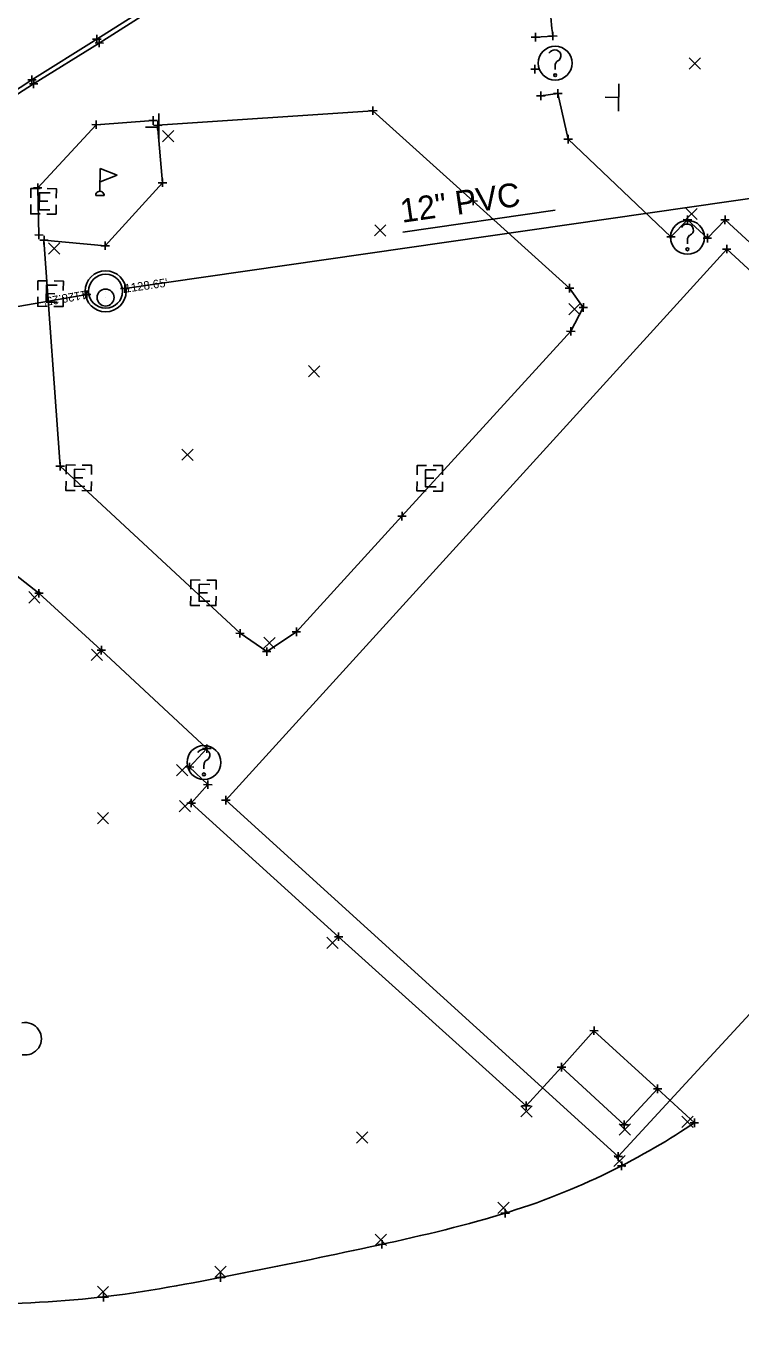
# Model space of a CAD drawing. Extents: x 142461 to 147261, y 511126 to 514697.
# Drawn here: x 145184.1 to 145268.4, y 512896.1 to 513050 of the extents above; entities that cross this region are included whole.
import ezdxf

# ---------------------------------------------------------------- set-up
doc = ezdxf.new("R2010")
doc.units = 0
for name, color, linetype in [('BD_X_Building', 7, 'Continuous'), ('DR_X_Cells', 7, 'Continuous'), ('DR_X_Elev_Flow', 7, 'Continuous'), ('DR_X_Storm_Sewer', 7, 'Continuous'), ('DR_X_Text', 7, 'Continuous'), ('GK_Drainage_Nodes', 7, 'Continuous'), ('PV_X_Curb', 7, 'Continuous'), ('PV_X_EOP', 7, 'Continuous'), ('PV_X_Walk', 7, 'Continuous'), ('RD_X_Cells', 7, 'Continuous'), ('RD_X_Misc_Items', 7, 'Continuous'), ('SC_Scratch1', 7, 'Continuous'), ('SN_X_Public', 7, 'Continuous'), ('SV_X_Random_Point', 7, 'Continuous'), ('SV_X_Shot_Marker', 7, 'Continuous'), ('UT_X_Electric_Cells', 7, 'Continuous'), ('VG_X_Cells', 7, 'Continuous')]:
    doc.layers.add(name, color=color, linetype=linetype)

msp = doc.modelspace()

# ---------------------------------------------------------------- linework, layer by layer
at = {"layer": 'BD_X_Building'}
msp.add_lwpolyline([(145253.97, 512916.68), (145313.24, 512980.9), (145266.75, 513023.71), (145207.7, 512958.7)], close=True, dxfattribs=at)
at = {"layer": 'DR_X_Cells'}
for centre, radius in [((145193.52, 513018.73), 2.42), ((145193.52, 513018.73), 2), ((145193.52, 513017.99), 1)]:
    msp.add_circle(centre, radius, dxfattribs=at)
at = {"layer": 'DR_X_Elev_Flow'}
for p, q in [((145190.79, 513018.34), (145191.79, 513018.34)), ((145191.29, 513018.84), (145191.29, 513017.84)), ((145191.29, 513018.34), (145191.29, 513018.34)), ((145195.28, 513019.06), (145196.28, 513019.06)), ((145195.78, 513019.56), (145195.78, 513018.56)), ((145195.78, 513019.06), (145195.78, 513019.06))]:
    msp.add_line(p, q, dxfattribs=at)
at = {"layer": 'DR_X_Storm_Sewer'}
for p, q in [((145195.78, 513019.06), (145275.88, 513030.6)), ((145191.29, 513018.34), (145030.57, 512990.68))]:
    msp.add_line(p, q, dxfattribs=at)
at = {"layer": 'DR_X_Text'}
msp.add_line((145246.52, 513028.29), (145228.56, 513025.7), dxfattribs=at)
at = {"layer": 'GK_Drainage_Nodes'}
for p, q in [((145193.52, 513020.74), (145193.52, 513020.74)), ((145193.52, 513018.73), (145193.52, 513018.73)), ((145193.52, 513018.73), (145193.52, 513018.73)), ((145193.52, 513017.99), (145193.52, 513017.99)), ((145193.52, 513016.74), (145193.52, 513016.74))]:
    msp.add_line(p, q, dxfattribs=at)
msp.add_circle((145193.52, 513018.73), 2, dxfattribs=at)
at = {"layer": 'PV_X_Curb'}
for p, q in [((145192.77, 513048.01), (145235.74, 513075.4)), ((145185.03, 513043.18), (145192.77, 513048.01)), ((145178.82, 513039.2), (145185.03, 513043.18))]:
    msp.add_line(p, q, dxfattribs=at)
msp.add_lwpolyline([(145186.25, 513024.75), (145193.47, 513024.1), (145200.22, 513031.53), (145199.65, 513038.31), (145225.04, 513040.03), (145236.86, 513029.37), (145248.21, 513019.09), (145249.84, 513016.82), (145248.38, 513014.01), (145228.46, 512992.2), (145216.01, 512978.56), (145212.52, 512976.23), (145209.37, 512978.39), (145188.17, 512998.09)], close=True, dxfattribs=at)
at = {"layer": 'PV_X_EOP'}
for p, q in [((145235.58, 513075.85), (145192.49, 513048.46)), ((145192.49, 513048.46), (145184.84, 513043.67)), ((145184.84, 513043.67), (145178.56, 513039.58))]:
    msp.add_line(p, q, dxfattribs=at)
at = {"layer": 'PV_X_Walk'}
for p, q in [((145244.21, 513048.7), (145246.27, 513048.83)), ((145246.85, 513042.05), (145244.84, 513041.78)), ((145248.06, 513036.67), (145246.85, 513042.05)), ((145260.18, 513025.16), (145248.06, 513036.67)), ((145262.13, 513027.17), (145260.18, 513025.16)), ((145264.48, 513024.99), (145262.13, 513027.17)), ((145266.56, 513027.15), (145264.48, 513024.99)), ((145286.66, 513008.67), (145266.56, 513027.15)), ((145185.66, 512983.11), (145180.12, 512987.45)), ((145193.01, 512976.4), (145185.66, 512983.11)), ((145205.45, 512964.79), (145193.01, 512976.4)), ((145203.41, 512962.61), (145205.45, 512964.79)), ((145205.58, 512960.54), (145203.41, 512962.61)), ((145203.6, 512958.37), (145205.58, 512960.54)), ((145221, 512942.6), (145203.6, 512958.37)), ((145243.1, 512922.67), (145221, 512942.6)), ((145251.1, 512931.51), (145247.27, 512927.21)), ((145258.61, 512924.66), (145251.1, 512931.51)), ((145247.27, 512927.21), (145243.1, 512922.67)), ((145262.94, 512920.64), (145258.61, 512924.66))]:
    msp.add_line(p, q, dxfattribs=at)
for points in [[(145185.66, 513025.36), (145185.52, 513030.95), (145192.41, 513038.38), (145199.12, 513038.88)], [(145247.27, 512927.21), (145254.67, 512920.41), (145258.61, 512924.66)]]:
    msp.add_lwpolyline(points, dxfattribs=at)
for points in [[(145246.27, 513048.83), (145245.85, 513051.17), (145245.79, 513056.41), (145252.55, 513065.11), (145258.38, 513070.36), (145263.1, 513072.97)], [(145064.73, 512959.34), (145063.58, 512957.75), (145061.55, 512953.72), (145062.14, 512946.4), (145065.23, 512938.47), (145073.35, 512928.85), (145086.5, 512918.18), (145106.96, 512910.53), (145125.95, 512904.95), (145143.43, 512899.62), (145159.95, 512899.19), (145176.54, 512899.04), (145192.88, 512899.67), (145208.86, 512902.71), (145224.67, 512905.94), (145240.68, 512909.6), (145253.08, 512914.56), (145260.17, 512918.77), (145262.94, 512920.64)], [(145063.98, 512925.11), (145069.77, 512919.92), (145080.69, 512909.67), (145103.07, 512901.33), (145123.63, 512895.37), (145142.03, 512889.72), (145159.63, 512889.13), (145176.81, 512888.85), (145194, 512889.65), (145209.87, 512893.18), (145224.9, 512894.34), (145240.29, 512892.09), (145248.15, 512887), (145251.76, 512882.95)]]:
    msp.add_open_spline(points, degree=3, dxfattribs=at)
at = {"layer": 'RD_X_Cells'}
for p, q in [((145192.85, 513030.53), (145192.88, 513033.23)), ((145194.87, 513032.41), (145192.86, 513031.63)), ((145192.88, 513033.23), (145194.87, 513032.41)), ((145192.86, 513031.63), (145192.86, 513031.63)), ((145192.35, 513030.04), (145193.35, 513030.03))]:
    msp.add_line(p, q, dxfattribs=at)
msp.add_arc((145192.85, 513030.03), 0.5, 359.4086, 179.4086, dxfattribs=at)
at = {"layer": 'RD_X_Misc_Items'}
for p, q in [((145246.53, 513044.88), (145246.53, 513045.36)), ((145262.13, 513024.33), (145262.14, 513024.81)), ((145205.12, 512962.4), (145205.12, 512962.87))]:
    msp.add_line(p, q, dxfattribs=at)
for centre, radius in [((145246.53, 513045.64), 2), ((145246.53, 513044.22), 0.17), ((145262.14, 513025.09), 2), ((145262.12, 513023.68), 0.17), ((145205.12, 512963.15), 2), ((145205.11, 512961.74), 0.17)]:
    msp.add_circle(centre, radius, dxfattribs=at)
for centre, radius, start, end in [((145246.47, 513046.45), 0.754, 88.324, 152.5385), ((145246.52, 513046.51), 0.688, 291.9329, 92.4584), ((145247.12, 513045.4), 0.587, 125.4618, 184.0829), ((145262.08, 513025.9), 0.754, 87.7326, 151.9471), ((145262.14, 513025.97), 0.688, 291.3416, 91.867), ((145262.72, 513024.85), 0.587, 124.8704, 183.4915), ((145205.07, 512963.96), 0.754, 87.7326, 151.9471), ((145205.12, 512964.03), 0.688, 291.3416, 91.867), ((145205.71, 512962.91), 0.587, 124.8704, 183.4915)]:
    msp.add_arc(centre, radius, start, end, dxfattribs=at)
at = {"layer": 'SN_X_Public'}
for p, q in [((145254.03, 513043.19), (145254, 513039.99)), ((145254.02, 513041.59), (145252.42, 513041.61)), ((145254.01, 513041.59), (145254.01, 513041.59)), ((145199.81, 513039.68), (145199.81, 513036.48)), ((145199.81, 513038.08), (145198.21, 513038.08)), ((145199.8, 513038.08), (145199.8, 513038.08))]:
    msp.add_line(p, q, dxfattribs=at)
at = {"layer": 'SV_X_Random_Point'}
for p, q in [((145262.32, 513044.93), (145263.65, 513046.26)), ((145262.32, 513046.26), (145263.65, 513044.93)), ((145200.22, 513036.37), (145201.56, 513037.69)), ((145200.23, 513037.7), (145201.55, 513036.36)), ((145261.92, 513027.19), (145263.27, 513028.51)), ((145261.94, 513028.53), (145263.26, 513027.18)), ((145225.23, 513025.25), (145226.58, 513026.57)), ((145225.25, 513026.58), (145226.57, 513025.23)), ((145186.77, 513023.12), (145188.12, 513024.44)), ((145186.79, 513024.46), (145188.11, 513023.11)), ((145248.14, 513015.97), (145249.49, 513017.29)), ((145248.15, 513017.3), (145249.47, 513015.95)), ((145217.43, 513008.62), (145218.77, 513009.94)), ((145217.44, 513009.96), (145218.76, 513008.61)), ((145202.5, 512998.79), (145203.85, 513000.11)), ((145202.52, 513000.12), (145203.84, 512998.78)), ((145184.45, 512981.96), (145185.8, 512983.29)), ((145184.46, 512983.3), (145185.78, 512981.95)), ((145212.15, 512976.59), (145213.5, 512977.91)), ((145212.16, 512977.92), (145213.48, 512976.58)), ((145191.83, 512975.18), (145193.17, 512976.51)), ((145191.84, 512976.52), (145193.16, 512975.17)), ((145201.87, 512961.59), (145203.22, 512962.91)), ((145201.89, 512962.93), (145203.21, 512961.58)), ((145202.21, 512957.33), (145203.56, 512958.66)), ((145202.22, 512958.67), (145203.54, 512957.32)), ((145192.55, 512955.9), (145193.88, 512957.24)), ((145192.55, 512957.24), (145193.88, 512955.9)), ((145219.61, 512941.2), (145220.95, 512942.53)), ((145219.62, 512942.54), (145220.94, 512941.19)), ((145242.47, 512921.34), (145243.82, 512922.66)), ((145242.48, 512922.67), (145243.8, 512921.32)), ((145261.46, 512920.1), (145262.81, 512921.42)), ((145261.48, 512921.43), (145262.8, 512920.08)), ((145254.08, 512919.2), (145255.42, 512920.52)), ((145254.09, 512920.54), (145255.41, 512919.19)), ((145223.09, 512918.24), (145224.42, 512919.58)), ((145223.09, 512919.58), (145224.42, 512918.24)), ((145253.45, 512915.48), (145254.8, 512916.8)), ((145253.47, 512916.81), (145254.79, 512915.46)), ((145239.75, 512909.97), (145241.09, 512911.29)), ((145239.76, 512911.3), (145241.08, 512909.95)), ((145225.3, 512906.19), (145226.65, 512907.51)), ((145225.32, 512907.52), (145226.64, 512906.17)), ((145206.38, 512902.41), (145207.72, 512903.73)), ((145206.39, 512903.74), (145207.71, 512902.39)), ((145192.53, 512900.04), (145193.88, 512901.36)), ((145192.55, 512901.37), (145193.87, 512900.03))]:
    msp.add_line(p, q, dxfattribs=at)
at = {"layer": 'SV_X_Shot_Marker'}
for p, q in [((145244.22, 513049.2), (145244.21, 513048.2)), ((145246.27, 513049.33), (145246.26, 513048.33)), ((145191.99, 513048.47), (145192.99, 513048.46)), ((145192.27, 513048.02), (145193.27, 513048.01)), ((145192.5, 513048.96), (145192.49, 513047.96)), ((145192.49, 513048.46), (145192.49, 513048.46)), ((145192.77, 513048.51), (145192.76, 513047.51)), ((145192.77, 513048.01), (145192.77, 513048.01)), ((145243.71, 513048.71), (145244.71, 513048.7)), ((145244.21, 513048.7), (145244.21, 513048.7)), ((145245.77, 513048.84), (145246.77, 513048.83)), ((145246.27, 513048.83), (145246.27, 513048.83)), ((145243.64, 513044.92), (145244.64, 513044.91)), ((145244.15, 513045.42), (145244.14, 513044.42)), ((145244.14, 513044.92), (145244.14, 513044.92)), ((145184.34, 513043.68), (145185.34, 513043.67)), ((145184.53, 513043.19), (145185.53, 513043.18)), ((145184.84, 513044.17), (145184.83, 513043.17)), ((145184.84, 513043.67), (145184.84, 513043.67)), ((145185.04, 513043.68), (145185.03, 513042.68)), ((145185.03, 513043.18), (145185.03, 513043.18)), ((145244.34, 513041.79), (145245.34, 513041.78)), ((145244.84, 513042.28), (145244.83, 513041.28)), ((145244.84, 513041.78), (145244.84, 513041.78)), ((145246.35, 513042.06), (145247.35, 513042.05)), ((145246.85, 513042.55), (145246.84, 513041.55)), ((145246.85, 513042.05), (145246.85, 513042.05)), ((145224.54, 513040.04), (145225.54, 513040.03)), ((145225.04, 513040.53), (145225.03, 513039.53)), ((145225.04, 513040.03), (145225.04, 513040.03)), ((145191.91, 513038.39), (145192.91, 513038.38)), ((145192.42, 513038.88), (145192.41, 513037.88)), ((145192.41, 513038.38), (145192.41, 513038.38)), ((145198.62, 513038.88), (145199.62, 513038.87)), ((145199.12, 513039.38), (145199.11, 513038.38)), ((145199.12, 513038.88), (145199.12, 513038.88)), ((145199.15, 513038.31), (145200.15, 513038.3)), ((145199.66, 513038.81), (145199.65, 513037.81)), ((145199.65, 513038.31), (145199.65, 513038.31)), ((145248.06, 513037.17), (145248.05, 513036.17)), ((145247.56, 513036.68), (145248.56, 513036.67)), ((145248.06, 513036.67), (145248.06, 513036.67)), ((145185.02, 513030.95), (145186.02, 513030.94)), ((145185.52, 513031.45), (145185.51, 513030.45)), ((145185.52, 513030.95), (145185.52, 513030.95)), ((145199.72, 513031.53), (145200.72, 513031.52)), ((145200.22, 513032.03), (145200.21, 513031.03)), ((145200.22, 513031.53), (145200.22, 513031.53)), ((145236.36, 513029.38), (145237.36, 513029.37)), ((145236.86, 513029.87), (145236.85, 513028.87)), ((145236.86, 513029.37), (145236.86, 513029.37)), ((145262.13, 513027.67), (145262.12, 513026.67)), ((145266.56, 513027.65), (145266.55, 513026.65)), ((145261.63, 513027.18), (145262.63, 513027.17)), ((145262.13, 513027.17), (145262.13, 513027.17)), ((145266.06, 513027.15), (145267.06, 513027.14)), ((145266.56, 513027.15), (145266.56, 513027.15)), ((145185.16, 513025.37), (145186.16, 513025.36)), ((145185.66, 513025.86), (145185.65, 513024.86)), ((145185.66, 513025.36), (145185.66, 513025.36)), ((145185.75, 513024.76), (145186.75, 513024.75)), ((145186.26, 513025.25), (145186.25, 513024.25)), ((145186.25, 513024.75), (145186.25, 513024.75)), ((145193.47, 513024.6), (145193.46, 513023.6)), ((145259.68, 513025.17), (145260.68, 513025.16)), ((145260.18, 513025.66), (145260.17, 513024.66)), ((145260.18, 513025.16), (145260.18, 513025.16)), ((145263.98, 513024.99), (145264.98, 513024.98)), ((145264.49, 513025.49), (145264.48, 513024.49)), ((145264.48, 513024.99), (145264.48, 513024.99)), ((145192.97, 513024.1), (145193.97, 513024.09)), ((145193.47, 513024.1), (145193.47, 513024.1)), ((145266.25, 513023.71), (145267.25, 513023.71)), ((145266.75, 513024.21), (145266.75, 513023.21)), ((145266.75, 513023.71), (145266.75, 513023.71)), ((145247.71, 513019.1), (145248.71, 513019.09)), ((145248.22, 513019.59), (145248.21, 513018.59)), ((145248.21, 513019.09), (145248.21, 513019.09)), ((145249.34, 513016.83), (145250.34, 513016.81)), ((145249.85, 513017.32), (145249.84, 513016.32)), ((145249.84, 513016.82), (145249.84, 513016.82)), ((145247.88, 513014.01), (145248.88, 513014)), ((145248.38, 513014.51), (145248.37, 513013.51)), ((145248.38, 513014.01), (145248.38, 513014.01)), ((145188.18, 512998.59), (145188.17, 512997.59)), ((145187.67, 512998.1), (145188.67, 512998.09)), ((145188.17, 512998.09), (145188.17, 512998.09)), ((145227.96, 512992.21), (145228.96, 512992.2)), ((145228.47, 512992.7), (145228.46, 512991.7)), ((145228.46, 512992.2), (145228.46, 512992.2)), ((145185.16, 512983.12), (145186.16, 512983.11)), ((145185.66, 512983.61), (145185.65, 512982.61)), ((145185.66, 512983.11), (145185.66, 512983.11)), ((145208.87, 512978.39), (145209.87, 512978.38)), ((145209.37, 512978.89), (145209.36, 512977.89)), ((145209.37, 512978.39), (145209.37, 512978.39)), ((145215.51, 512978.56), (145216.51, 512978.55)), ((145216.02, 512979.06), (145216.01, 512978.06)), ((145216.01, 512978.56), (145216.01, 512978.56)), ((145193.02, 512976.9), (145193.01, 512975.9)), ((145212.53, 512976.73), (145212.52, 512975.73)), ((145192.51, 512976.4), (145193.51, 512976.39)), ((145193.01, 512976.4), (145193.01, 512976.4)), ((145212.02, 512976.24), (145213.02, 512976.23)), ((145212.52, 512976.23), (145212.52, 512976.23)), ((145204.95, 512964.79), (145205.95, 512964.78)), ((145205.45, 512965.29), (145205.44, 512964.29)), ((145205.45, 512964.79), (145205.45, 512964.79)), ((145203.42, 512963.11), (145203.41, 512962.11)), ((145202.91, 512962.62), (145203.91, 512962.61)), ((145203.41, 512962.61), (145203.41, 512962.61)), ((145205.08, 512960.54), (145206.08, 512960.53)), ((145205.58, 512961.04), (145205.57, 512960.04)), ((145205.58, 512960.54), (145205.58, 512960.54)), ((145203.1, 512958.37), (145204.1, 512958.36)), ((145203.61, 512958.87), (145203.6, 512957.87)), ((145203.6, 512958.37), (145203.6, 512958.37)), ((145207.2, 512958.7), (145208.2, 512958.7)), ((145207.7, 512959.2), (145207.7, 512958.2)), ((145207.7, 512958.7), (145207.7, 512958.7)), ((145221, 512943.1), (145220.99, 512942.1)), ((145220.5, 512942.6), (145221.5, 512942.59)), ((145221, 512942.6), (145221, 512942.6)), ((145250.6, 512931.52), (145251.6, 512931.51)), ((145251.11, 512932.01), (145251.1, 512931.01)), ((145251.1, 512931.51), (145251.1, 512931.51)), ((145247.28, 512927.71), (145247.27, 512926.71)), ((145246.77, 512927.21), (145247.77, 512927.2)), ((145247.27, 512927.21), (145247.27, 512927.21)), ((145258.11, 512924.66), (145259.11, 512924.65)), ((145258.61, 512925.16), (145258.6, 512924.16)), ((145258.61, 512924.66), (145258.61, 512924.66)), ((145243.11, 512923.17), (145243.1, 512922.17)), ((145242.6, 512922.67), (145243.6, 512922.66)), ((145243.1, 512922.67), (145243.1, 512922.67)), ((145254.17, 512920.42), (145255.17, 512920.41)), ((145254.67, 512920.91), (145254.66, 512919.91)), ((145254.67, 512920.41), (145254.67, 512920.41)), ((145262.44, 512920.65), (145263.44, 512920.64)), ((145262.95, 512921.14), (145262.94, 512920.14)), ((145262.94, 512920.64), (145262.94, 512920.64)), ((145253.97, 512917.18), (145253.97, 512916.18)), ((145253.47, 512916.68), (145254.47, 512916.68)), ((145253.87, 512915.57), (145254.87, 512915.56)), ((145253.97, 512916.68), (145253.97, 512916.68)), ((145254.37, 512916.07), (145254.36, 512915.07)), ((145254.37, 512915.57), (145254.37, 512915.57)), ((145240.13, 512909.99), (145241.13, 512909.98)), ((145240.63, 512910.49), (145240.62, 512909.49)), ((145240.63, 512909.99), (145240.63, 512909.99)), ((145225.61, 512906.32), (145226.61, 512906.31)), ((145226.11, 512906.82), (145226.1, 512905.82)), ((145226.11, 512906.32), (145226.11, 512906.32)), ((145207.08, 512902.9), (145207.07, 512901.9)), ((145206.57, 512902.4), (145207.57, 512902.39)), ((145207.07, 512902.4), (145207.07, 512902.4)), ((145192.76, 512900.09), (145193.76, 512900.07)), ((145193.27, 512900.58), (145193.26, 512899.58)), ((145193.26, 512900.08), (145193.26, 512900.08))]:
    msp.add_line(p, q, dxfattribs=at)
at = {"layer": 'UT_X_Electric_Cells'}
for p, q in [((145185.71, 513029.35), (145186.71, 513029.34)), ((145186.21, 513029.34), (145186.21, 513029.34)), ((145186.53, 513018.45), (145187.53, 513018.44)), ((145187.03, 513018.45), (145187.03, 513018.45)), ((145189.85, 512996.73), (145190.85, 512996.72)), ((145190.35, 512996.73), (145190.35, 512996.73)), ((145231.24, 512996.68), (145232.24, 512996.67)), ((145231.74, 512996.67), (145231.74, 512996.67)), ((145204.55, 512983.17), (145205.55, 512983.16)), ((145205.05, 512983.17), (145205.05, 512983.17))]:
    msp.add_line(p, q, dxfattribs=at)
for points in [[(145185.82, 513030.85), (145184.72, 513030.86), (145184.71, 513029.76)], [(145187.71, 513029.73), (145187.72, 513030.83), (145186.62, 513030.84)], [(145186.97, 513030.33), (145185.72, 513030.35), (145185.7, 513028.35), (145186.95, 513028.33)], [(145184.7, 513028.96), (145184.69, 513027.86), (145185.79, 513027.85)], [(145186.59, 513027.84), (145187.69, 513027.83), (145187.7, 513028.93)], [(145186.64, 513019.95), (145185.54, 513019.96), (145185.53, 513018.86)], [(145188.53, 513018.83), (145188.54, 513019.93), (145187.44, 513019.95)], [(145187.79, 513019.44), (145186.54, 513019.45), (145186.52, 513017.45), (145187.77, 513017.44)], [(145185.52, 513018.06), (145185.51, 513016.96), (145186.61, 513016.95)], [(145187.41, 513016.95), (145188.51, 513016.93), (145188.52, 513018.03)], [(145189.97, 512998.23), (145188.87, 512998.24), (145188.85, 512997.14)], [(145191.11, 512997.72), (145189.86, 512997.73), (145189.84, 512995.73), (145191.09, 512995.72)], [(145191.85, 512997.11), (145191.87, 512998.21), (145190.77, 512998.22)], [(145231.36, 512998.18), (145230.26, 512998.19), (145230.25, 512997.09)], [(145232.5, 512997.66), (145231.25, 512997.68), (145231.23, 512995.68), (145232.48, 512995.66)], [(145233.25, 512997.06), (145233.26, 512998.16), (145232.16, 512998.17)], [(145188.85, 512996.34), (145188.83, 512995.24), (145189.93, 512995.23)], [(145190.73, 512995.22), (145191.83, 512995.21), (145191.85, 512996.31)], [(145230.24, 512996.29), (145230.23, 512995.19), (145231.33, 512995.18)], [(145232.13, 512995.17), (145233.23, 512995.16), (145233.24, 512996.26)], [(145204.67, 512984.67), (145203.57, 512984.68), (145203.55, 512983.58)], [(145206.55, 512983.55), (145206.57, 512984.65), (145205.47, 512984.66)], [(145205.81, 512984.16), (145204.56, 512984.17), (145204.54, 512982.17), (145205.79, 512982.16)], [(145203.55, 512982.78), (145203.53, 512981.68), (145204.63, 512981.67)], [(145205.43, 512981.66), (145206.53, 512981.65), (145206.55, 512982.75)]]:
    msp.add_lwpolyline(points, dxfattribs=at)
at = {"layer": 'VG_X_Cells'}
msp.add_arc((145184.04, 512930.56), 1.91, 259.1453, 101.4596, dxfattribs=at)

# ---------------------------------------------------------------- texts
at = {"layer": 'DR_X_Text'}
msp.add_text('12" PVC', height=2.8, rotation=8.1965, dxfattribs=at).set_placement((145228.47, 513026.8))
at = {"layer": 'SC_Scratch1'}
for s, rotation, p in [("1128.65'", 8.1965, (145195.85, 513018.56)), ("1128.25'", 189.7645, (145191.2, 513018.83))]:
    msp.add_text(s, height=1, rotation=rotation, dxfattribs=at).set_placement(p)

doc.saveas('drawing.dxf')
